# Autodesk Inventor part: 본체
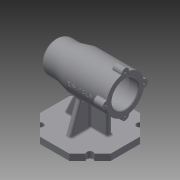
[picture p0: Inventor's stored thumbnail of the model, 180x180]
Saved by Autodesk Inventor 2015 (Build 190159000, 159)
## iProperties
Created: 2019-12
Part Number: 본체
Material: 일반
Document SubType Name: Modeling
Designer: 1010101
Density: 1 g/cm^3
Appearance: 기본값
Author: 1010101
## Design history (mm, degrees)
sketch "스케치1"
  geometry: L1 (23.196, 56)-(56, 23.196); L2 (56, 23.196)-(56, -23.196); L3 (56, -23.196)-(23.196, -56); L4 (23.196, -56)-(-23.196, -56); L5 (-23.196, -56)-(-56, -23.196); L6 (-56, -23.196)-(-56, 23.196); L7 (-56, 23.196)-(-23.196, 56); L8 (-23.196, 56)-(23.196, 56); C1 r 56 at (0, 0); 2 further points
  constraints: 16 end point, 2 coincident, 1 centre point, 1 horizontal, 1 tangent, 17 other
  dimensions: "d0" = 112 diameter of C1
extrude "돌출1" new body sketch "스케치1" distance "d1" = 10; taper "d2" = 0 deg
sketch "스케치2"
  geometry: L1 (23.196, 56)-(-23.196, 56) reference; L2 (-56, 23.196)-(-56, -23.196) reference; L3 (-23.196, -56)-(23.196, -56) reference; L4 (56, -23.196)-(56, 23.196) reference; L5 (-38, -4)-(31, -4); L6 (31, -4)-(31, 4); L7 (31, 4)-(-38, 4); L8 (-38, 4)-(-38, -4); L9 (-4, -36)-(4, -36); L10 (4, -36)-(4, 36); L11 (4, 36)-(-4, 36); L12 (-4, 36)-(-4, -36); 1 further point
  constraints: 16 end point, 4 parallel, 2 horizontal, 2 perpendicular
  dimensions: "d3" = 4 distance from line of point (0, 0) L5; "d4" = 4 distance from line of L10 point (0, 0); "d5" = 8 distance between parallel lines of L10 L12; "d6" = 8 distance between parallel lines of L5 L7; "d7" = 20 distance between parallel lines of L1 L11; "d8" = 20 distance between parallel lines of L3 L9; "d9" = 25 distance between parallel lines of L4 L6; "d10" = 18 distance between parallel lines of L8 L2
extrude "돌출2" join sketch "스케치2" distance "d11" = 70; taper "d12" = 0 deg
feature "면 기울기1" dims angle "d13" = 20 deg
feature "면 기울기2" dims angle "d14" = 20 deg
feature "면 기울기3" dims angle "d15" = 25 deg
sketch "스케치3"
  geometry: L1 (56, 10)-(56, 0) reference; L2 (56, 0)-(-56, 0) reference; L3 (-56, 0)-(-56, 10) reference; L4 (-56, 10)-(-31, 10) reference; L5 (-31, 10)-(-31, 80) reference; L6 (-31, 80)-(5.358, 80) reference; L7 (5.358, 80)-(38, 10) reference; L8 (38, 10)-(56, 10) reference; L9 (56, 80)-(-56, 80); L10 (-56, 80)-(-56, 110); L11 (-56, 110)-(11, 110); L12 (11, 110)-(31, 105); L13 (31, 105)-(56, 105); L14 (56, 105)-(56, 80); 3 further points
  constraints: 12 end point, 3 perpendicular, 2 midpoint, 1 horizontal, 1 parallel, 1 vertical alignment
  dimensions: "d16" = 112 distance of L9.start L9.end; "d17" = 25 distance of L12.end L13.end; "d18" = 45 horizontal distance of L11.end L13.end; "d19" = 30 distance between parallel lines of L9 L11; "d20" = 25 distance of L13.end L9.start; "d21" = 80 distance between parallel lines of L2 L9
revolve "회전1" sketch "스케치3" stored, may be unused: angle "d22" = 90 deg
sketch "스케치4"
  geometry: C1 r 30 at (0, 0) reference; C2 r 21 at (0, 0); 1 further point
  constraints: 1 centre point, 1 coincident
  dimensions: "d23" = 42 diameter of C2
extrude "돌출3" cut sketch "스케치4" distance "d24" = 15; taper "d25" = 0 deg
sketch "스케치5"
  geometry: C1 r 21 at (0, 0) reference; C2 r 24 at (0, 0); 1 further point
  constraints: 1 centre point, 1 coincident
  dimensions: "d26" = 48 diameter of C2
extrude "돌출4" cut sketch "스케치5" distance "d27" = 54; taper "d28" = 0 deg
sketch "스케치6"
  geometry: C1 r 24 at (0, 0) reference; C2 r 21 at (0, 0); 1 further point
  constraints: 1 centre point, 1 coincident
  dimensions: "d29" = 42 diameter of C2
extrude "돌출5" cut sketch "스케치6" distance "d30" = 12; taper "d31" = 0 deg
sketch "스케치7"
  geometry: C1 r 21 at (0, 0) reference; C2 r 17.5 at (0, 0); 1 further point
  constraints: 1 centre point, 1 coincident
  dimensions: "d32" = 35 diameter of C2
extrude "돌출6" cut sketch "스케치7" distance "d33" = 18; taper "d34" = 0 deg
sketch "스케치8"
  geometry: C1 r 17.5 at (0, 0) reference; C2 r 16 at (0, 0); 1 further point
  constraints: 1 centre point, 1 coincident
  dimensions: "d35" = 32 diameter of C2
extrude "돌출7" cut sketch "스케치8" distance "d36" = 4; taper "d37" = 0 deg
sketch "스케치9"
  geometry: C1 r 16 at (0, 0) reference; C2 r 10.5 at (0, 0); 1 further point
  constraints: 1 centre point, 1 coincident
  dimensions: "d38" = 21 diameter of C2
extrude "돌출8" cut sketch "스케치9" distance "d39" = 3; taper "d40" = 0 deg
fillet "모깎기1" dims "d41" = 3
fillet "모깎기2" dims "d42" = 0.3
fillet "모깎기3" dims "d43" = 3
chamfer "모따기1" distance "d44" = 1; stored, may be unused: second distance "d45" = 2, angle "d46" = 45 deg
sketch "스케치10"
  geometry: C1 r 6 at (-30, 0); 3 further points
  constraints: 2 horizontal alignment, 1 centre point, 1 coincident, 1 other
  dimensions: "d47" = 12 diameter of C1
extrude "돌출9" join sketch "스케치10" distance "d48" = 16; taper "d49" = 0 deg
fillet "모깎기4" dims "d50" = 3
fillet "모깎기5" dims "d51" = 1
sketch "스케치11"
  geometry: A1 r 6 centre (0, 0) between (-0.171, 5.998) and (-0.171, -5.998) reference; 1 further point
hole "구멍1" sketch "스케치11" at (0, 0) diameter "d52" = 3.242; stored, may be unused: countersink angle "d56" = 90 deg, drill point angle "d58" = 118 deg; dims "d53" = 8, "d54" = 4, "d55" = 2, "d57" = 11
sketch "스케치12"
  geometry: L1 (23.196, -56)-(56, -23.196) reference; C1 r 5 at (39.598, -39.598); 1 further point
  constraints: 1 centre point, 1 midpoint
  dimensions: "d62" = 10 diameter of C1
extrude "돌출10" cut sketch "스케치12" stored distance "d63" = 16; taper "d64" = 0 deg
fillet "모깎기6" dims "d65" = 3
fillet "모깎기7" dims "d66" = 3
fillet "모깎기8" dims "d67" = 10
fillet "모깎기9" dims "d68" = 3
fillet "모깎기10" dims "d69" = 3
node "작업 평면1"
sketch "스케치13"
  geometry: L1 (33.5, 29.226)-(33.5, 6.771) reference; L2 (0.696, -80)-(-45.696, -80) reference; 2 further points
  constraints: 1 other
  dimensions: "d70" = 41 distance from line of point (-7.5, 0) L1; "d71" = 80 distance from line of L2 point (-7.5, 0)
feature "엠보싱1" sketch "스케치13" dims "d0" = 112, "d72" = 0.5, "d73" = 0
node "솔리드1"
pattern_circular "원형 패턴1" dims "d60" = 360 deg
mirror "대칭1"
mirror "대칭2"
node "절단 모서리 투영1"
